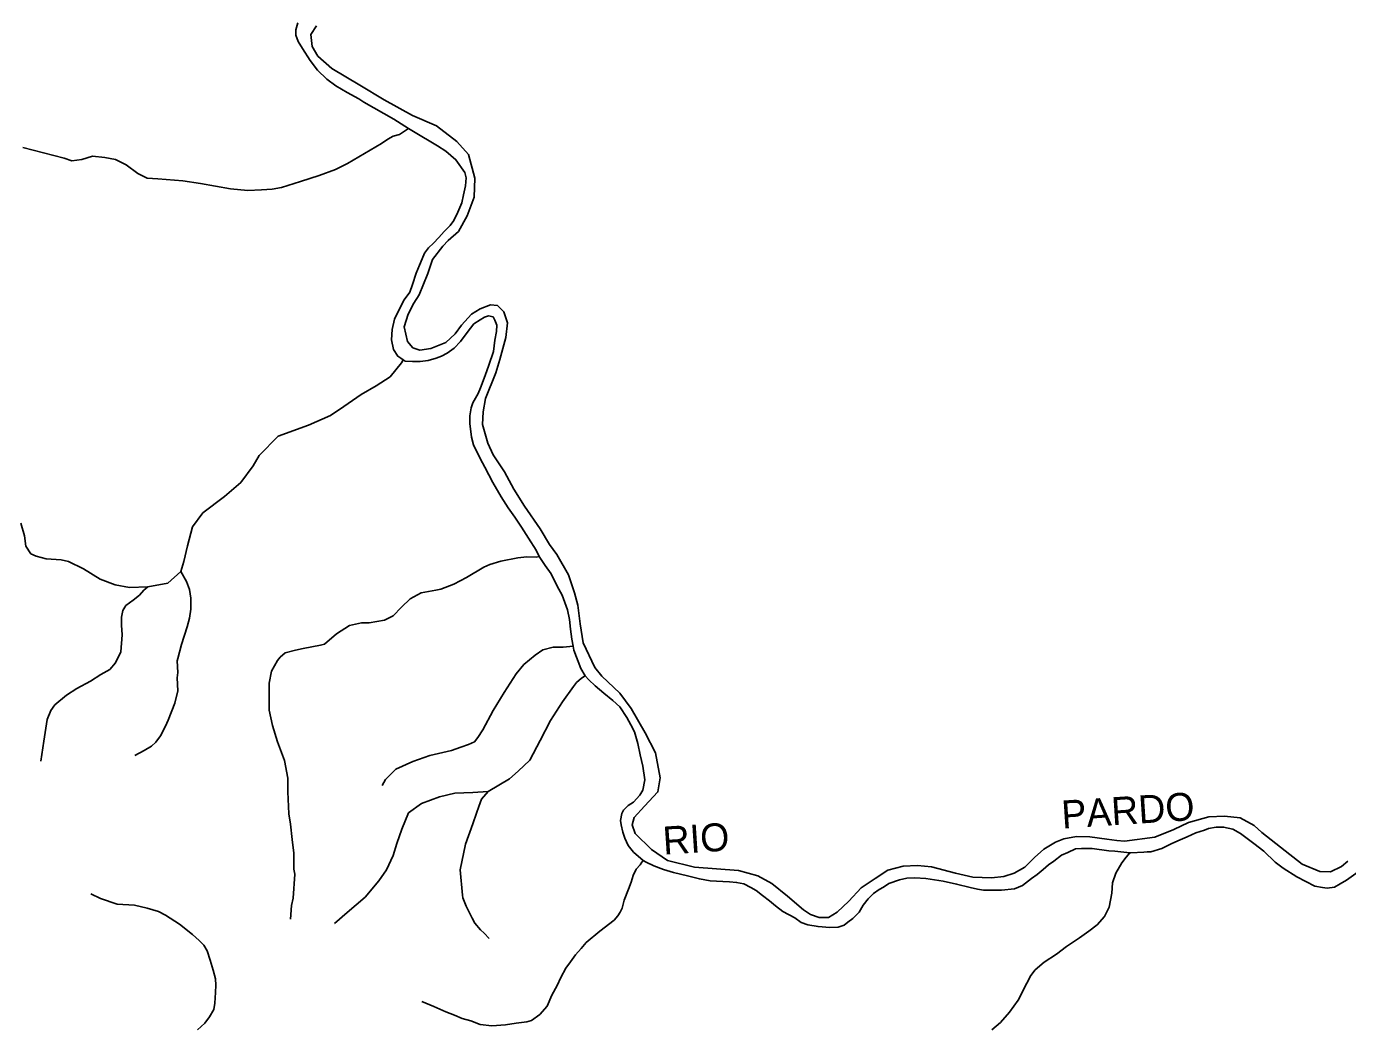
# Model space of a CAD drawing. Extents: x 436.3 to 500.4, y 8231 to 8286.4.
# Drawn here: x 483.31 to 492.75, y 8265.76 to 8272.92 of the extents above; entities that cross this region are included whole.
import ezdxf
from ezdxf.enums import TextEntityAlignment as Align

# ---------------------------------------------------------------- set-up
doc = ezdxf.new("R2010")
doc.units = 0
doc.header["$LTSCALE"] = 0.08
doc.linetypes.add('LONG_DASHED', pattern=[7.5, 6, -1.5])
doc.layers.add('2', color=7, linetype='Continuous', lineweight=25)
doc.layers.add('9', color=7, linetype='LONG_DASHED', lineweight=25)
doc.layers.add('61', color=7, linetype='Continuous')

msp = doc.modelspace()

# ---------------------------------------------------------------- linework, layer by layer
at = {"layer": '2'}
for points in [[(486.0404, 8272.1863), (485.9354, 8272.2526), (485.7207, 8272.3743), (485.6844, 8272.3972), (485.6006, 8272.443), (485.5205, 8272.4909), (485.4557, 8272.5386), (485.389, 8272.6016), (485.3376, 8272.6724), (485.2824, 8272.7584), (485.2518, 8272.8081), (485.2355, 8272.8515), (485.2337, 8272.8897), (485.2489, 8272.9413)], [(488.0829, 8266.9074), (487.8892, 8266.9559), (487.7758, 8267.0349), (487.6591, 8267.1491), (487.6361, 8267.21), (487.6514, 8267.2634), (487.7252, 8267.3446), (487.82, 8267.4463), (487.8366, 8267.5464), (487.8031, 8267.7243), (487.7304, 8267.8688), (487.6299, 8268.0412), (487.5495, 8268.1507), (487.4211, 8268.2729), (487.3709, 8268.3341), (487.2871, 8268.5122), (487.2648, 8268.6458), (487.2481, 8268.7794), (487.2259, 8268.8686), (487.1813, 8268.9967), (487.0976, 8269.1415), (487.0475, 8269.2139), (486.9805, 8269.3253), (486.869, 8269.4869), (486.791, 8269.6095), (486.7241, 8269.7322), (486.6447, 8269.8538), (486.6058, 8269.9375), (486.5669, 8270.0715), (486.5726, 8270.1608), (486.5896, 8270.2558), (486.6625, 8270.4402), (486.6905, 8270.5352), (486.7356, 8270.6917), (486.7469, 8270.7979), (486.7191, 8270.8761), (486.6745, 8270.9207), (486.6242, 8270.9263), (486.5515, 8270.8983), (486.49, 8270.8592), (486.4172, 8270.7808), (486.3724, 8270.7193), (486.3053, 8270.6578), (486.199, 8270.6129), (486.1208, 8270.6017), (486.0706, 8270.6184), (486.0315, 8270.6631), (486.0093, 8270.7693), (486.0374, 8270.8588), (486.0767, 8270.9371), (486.1159, 8270.9986), (486.1776, 8271.1496), (486.2113, 8271.2504), (486.2841, 8271.3454), (486.3232, 8271.3846), (486.3957, 8271.4502), (486.4573, 8271.5621), (486.5077, 8271.6963), (486.5135, 8271.8306), (486.4683, 8271.9989), (486.3853, 8272.0936), (486.2402, 8272.2055), (486.067, 8272.2782), (485.8659, 8272.3902), (485.6928, 8272.4965), (485.4918, 8272.6141), (485.3913, 8272.7037), (485.3522, 8272.7708), (485.3408, 8272.8566), (485.3818, 8272.9204)], [(486.4522, 8271.8331), (486.4423, 8271.8706), (486.3776, 8271.9623), (486.3071, 8272.0234), (486.2461, 8272.0616), (486.0756, 8272.1645), (486.0404, 8272.1863)], [(486.3373, 8271.4932), (486.3641, 8271.5295), (486.3928, 8271.5887), (486.4196, 8271.6536), (486.433, 8271.711), (486.4464, 8271.7759), (486.4522, 8271.8331)], [(486.0023, 8270.5329), (485.9853, 8270.5441), (485.9632, 8270.5588), (485.9328, 8270.6065), (485.9176, 8270.6771), (485.9235, 8270.7496), (485.9389, 8270.8241), (485.9733, 8270.8928), (486.0078, 8270.9616), (486.0501, 8271.0163), (486.0692, 8271.0718), (486.0941, 8271.1519), (486.1171, 8271.2092), (486.1362, 8271.2551), (486.1534, 8271.2951), (486.1822, 8271.3333), (486.2185, 8271.3658), (486.2552, 8271.4073), (486.2934, 8271.4493), (486.3373, 8271.4932)], [(486.9715, 8269.1282), (486.9505, 8269.1742), (486.8969, 8269.2591), (486.8455, 8269.3371), (486.7998, 8269.4094), (486.7522, 8269.4759), (486.7008, 8269.554), (486.6418, 8269.6568), (486.5845, 8269.7665), (486.5502, 8269.8274), (486.5046, 8269.9265), (486.4894, 8269.9817), (486.4763, 8270.077), (486.4783, 8270.1323), (486.486, 8270.1895), (486.4994, 8270.2257), (486.5379, 8270.2918), (486.5532, 8270.3338), (486.5878, 8270.4215), (486.6126, 8270.496), (486.6453, 8270.5932), (486.6568, 8270.6734), (486.6683, 8270.7344), (486.6703, 8270.7801), (486.6571, 8270.8165), (486.6438, 8270.8393), (486.6113, 8270.8469), (486.5828, 8270.8374), (486.5512, 8270.8189), (486.5053, 8270.7901), (486.4594, 8270.7272), (486.4097, 8270.6642), (486.3658, 8270.6164), (486.3161, 8270.5801), (486.2742, 8270.5591), (486.236, 8270.5438), (486.1787, 8270.5285), (486.1234, 8270.5208), (486.0681, 8270.5208), (486.0147, 8270.5246), (486.0023, 8270.5329)], [(487.2149, 8268.4865), (487.2058, 8268.5365), (487.1965, 8268.6081), (487.1889, 8268.6785), (487.1751, 8268.7465), (487.137, 8268.8511), (487.1009, 8268.9156), (487.059, 8269.0031), (487.0149, 8269.0647), (486.9715, 8269.1282)], [(487.3004, 8268.2765), (487.2708, 8268.327), (487.2207, 8268.4583), (487.2149, 8268.4865)], [(487.6072, 8267.0631), (487.5842, 8267.1163), (487.5709, 8267.158), (487.5575, 8267.211), (487.5537, 8267.2415), (487.5631, 8267.2908), (487.5745, 8267.3155), (487.6091, 8267.3491), (487.6454, 8267.372), (487.6911, 8267.4232), (487.7139, 8267.4593), (487.7271, 8267.5315), (487.7137, 8267.6301), (487.6947, 8267.7118), (487.6774, 8267.7915), (487.6523, 8267.8742), (487.6275, 8267.9254), (487.599, 8267.9766), (487.5494, 8268.0545), (487.4998, 8268.0981), (487.435, 8268.1511), (487.3717, 8268.2036), (487.3279, 8268.2468), (487.3004, 8268.2765)], [(492.7476, 8266.9504), (492.7029, 8266.9136), (492.6248, 8266.8747), (492.5468, 8266.8781), (492.421, 8266.931), (492.2676, 8267.0505), (492.1337, 8267.1562), (492.0778, 8267.2062), (491.9774, 8267.2619), (491.8658, 8267.2731), (491.7544, 8267.2675), (491.6095, 8267.2286), (491.5038, 8267.1786), (491.3702, 8267.123), (491.1529, 8267.0953), (491.0988, 8267.0984), (491.0264, 8267.1096), (490.9039, 8267.1263), (490.8092, 8267.1264), (490.7201, 8267.1097), (490.6589, 8267.0875), (490.5754, 8267.0375), (490.5087, 8266.9763), (490.4419, 8266.9096), (490.364, 8266.8651), (490.2916, 8266.8429), (490.2026, 8266.8319), (490.0688, 8266.8375), (489.9464, 8266.8653), (489.7736, 8266.9098), (489.6733, 8266.9209), (489.573, 8266.9153), (489.4617, 8266.8876), (489.3726, 8266.8264), (489.2724, 8266.7598), (489.1834, 8266.6653), (489.1, 8266.5874), (489.0387, 8266.5485), (488.9718, 8266.5485), (488.9105, 8266.5707), (488.8603, 8266.604)], [(492.8209, 8266.8747), (492.739, 8266.8158), (492.6934, 8266.7892), (492.6534, 8266.7665), (492.6001, 8266.7589), (492.5677, 8266.7627), (492.5115, 8266.7731), (492.3839, 8266.8396), (492.2867, 8266.9003), (492.2276, 8266.944), (492.1475, 8267.0219), (492.077, 8267.0769), (491.9818, 8267.1491), (491.9253, 8267.1792), (491.8605, 8267.1944), (491.8073, 8267.1944), (491.7521, 8267.1849), (491.7236, 8267.1735), (491.6628, 8267.1546), (491.6001, 8267.1262), (491.5335, 8267.0957), (491.486, 8267.0749), (491.4194, 8267.0407), (491.3406, 8267.0178), (491.3141, 8267.0178), (491.2906, 8267.0166), (491.1988, 8267.0119), (491.1911, 8267.0115)], [(487.7143, 8266.9565), (487.6453, 8267.0158), (487.6072, 8267.0631)], [(491.1911, 8267.0115), (491.084, 8267.0236), (491.0403, 8267.0255), (490.9205, 8267.0426), (490.8444, 8267.0427), (490.8026, 8267.0389), (490.7475, 8267.0124), (490.7019, 8266.9934), (490.6468, 8266.9517), (490.6107, 8266.925), (490.5727, 8266.8909), (490.5291, 8266.8549), (490.4892, 8266.8265), (490.4233, 8266.7765), (490.3682, 8266.7536), (490.2731, 8266.7442), (490.2085, 8266.7442), (490.1458, 8266.7442), (490.102, 8266.7518), (490.0507, 8266.7633), (489.9537, 8266.788), (489.8567, 8266.8089), (489.7332, 8266.8279), (489.656, 8266.8331), (489.597, 8266.8293), (489.5458, 8266.8179), (489.4697, 8266.7914), (489.4317, 8266.7667), (489.3994, 8266.7477), (489.3595, 8266.7211), (489.3216, 8266.6832), (489.2874, 8266.6358), (489.2569, 8266.5864), (489.2133, 8266.5428), (489.1772, 8266.5163), (489.1506, 8266.4935), (489.1069, 8266.4803), (489.048, 8266.4765), (488.9642, 8266.484), (488.8919, 8266.4973), (488.8443, 8266.5124), (488.7986, 8266.5465), (488.7117, 8266.5912), (488.6603, 8266.633), (488.6164, 8266.669), (488.5669, 8266.705), (488.5211, 8266.7409), (488.485, 8266.7638), (488.4336, 8266.7884), (488.3821, 8266.7997), (488.3326, 8266.8035), (488.285, 8266.8053), (488.1936, 8266.8109), (488.1174, 8266.8241), (488.0323, 8266.8456), (487.9313, 8266.8701)], [(487.9313, 8266.8701), (487.8608, 8266.8909), (487.7907, 8266.9191), (487.7357, 8266.945), (487.7143, 8266.9565)], [(488.8603, 8266.604), (488.7469, 8266.7024), (488.6352, 8266.7912), (488.5348, 8266.8467), (488.3953, 8266.8855), (488.2391, 8266.8965), (488.0829, 8266.9074)]]:
    msp.add_lwpolyline(points, dxfattribs=at)
at = {"layer": '9'}
for p, q in [((486.9509, 8269.1227), (486.9715, 8269.1282)), ((487.2737, 8268.2597), (487.3004, 8268.2765))]:
    msp.add_line(p, q, dxfattribs=at)
for points in [[(486.0404, 8272.1863), (485.9756, 8272.1439), (485.9302, 8272.1311), (485.8921, 8272.1093), (485.8468, 8272.0784), (485.6037, 8271.9358), (485.5188, 8271.8932), (485.4009, 8271.8506), (485.2688, 8271.808), (485.1319, 8271.7654), (485.0659, 8271.7512), (484.9905, 8271.7465), (484.8915, 8271.7417), (484.769, 8271.7558), (484.5549, 8271.794), (484.4276, 8271.8129), (484.2485, 8271.827), (484.1731, 8271.8317), (484.1072, 8271.8647), (484.0225, 8271.9261), (483.9471, 8271.9638), (483.8718, 8271.978), (483.7823, 8271.9874), (483.7068, 8271.9637), (483.6362, 8271.9542), (483.5796, 8271.9731), (483.286, 8272.0493)], [(484.4141, 8269.021), (484.4358, 8269.0915), (484.462, 8269.2044), (484.497, 8269.3389), (484.571, 8269.4388), (484.7248, 8269.5574), (484.8422, 8269.6574), (484.9293, 8269.7748), (484.9728, 8269.8487), (485.1078, 8269.9878), (485.3251, 8270.0662), (485.4815, 8270.1358), (485.5787, 8270.1994), (485.7005, 8270.2863), (485.8091, 8270.3472), (485.9092, 8270.4125), (485.9896, 8270.5115), (486.0023, 8270.5329)], [(483.271, 8269.3672), (483.2982, 8269.2758), (483.3072, 8269.2027), (483.3436, 8269.1479), (483.3801, 8269.1296), (483.4531, 8269.1114), (483.5592, 8269.1041), (483.6112, 8269.0911), (483.7196, 8269.0391), (483.8366, 8268.9654), (483.945, 8268.9263), (484.0463, 8268.9057), (484.1775, 8268.9102)], [(485.197, 8266.5363), (485.203, 8266.6334), (485.2152, 8266.6879), (485.2272, 8266.8578), (485.2211, 8266.8941), (485.2209, 8267.0094), (485.2086, 8267.1065), (485.1962, 8267.2157), (485.1839, 8267.2884), (485.1777, 8267.4463), (485.1777, 8267.5434), (485.1532, 8267.6709), (485.1043, 8267.8044), (485.0676, 8267.9198), (485.0433, 8268.0292), (485.0433, 8268.1203), (485.0433, 8268.2237), (485.0616, 8268.309), (485.1047, 8268.3855), (485.123, 8268.4099), (485.1597, 8268.4404), (485.233, 8268.4587), (485.2879, 8268.4711), (485.4101, 8268.4956), (485.4406, 8268.5018), (485.5261, 8268.575), (485.6177, 8268.636), (485.7036, 8268.6549), (485.7585, 8268.655), (485.8684, 8268.6734), (485.9295, 8268.704), (485.9906, 8268.7649), (486.0517, 8268.826), (486.131, 8268.8687), (486.2348, 8268.8872), (486.2715, 8268.8934), (486.363, 8268.9301), (486.4546, 8268.9789), (486.5767, 8269.0522), (486.6195, 8269.0706), (486.6988, 8269.095), (486.8208, 8269.1195), (486.8841, 8269.1261), (486.9509, 8269.1227)], [(484.0863, 8267.7067), (484.1518, 8267.7415), (484.2042, 8267.772), (484.2347, 8267.8024), (484.2696, 8267.846), (484.3046, 8267.9156), (484.322, 8267.9591), (484.3702, 8268.081), (484.3924, 8268.1693), (484.3881, 8268.2607), (484.3925, 8268.2999), (484.3882, 8268.3827), (484.3926, 8268.4001), (484.419, 8268.4995), (484.4584, 8268.6259), (484.476, 8268.687), (484.4849, 8268.7524), (484.485, 8268.8308), (484.4763, 8268.8919), (484.4546, 8268.9485), (484.4141, 8269.021)], [(484.1775, 8268.9102), (484.3209, 8268.9381), (484.4141, 8269.021)], [(483.4139, 8267.6657), (483.4352, 8267.8076), (483.4494, 8267.9019), (483.4581, 8267.9628), (483.4844, 8268.0281), (483.5149, 8268.0671), (483.5978, 8268.1368), (483.6719, 8268.1846), (483.7679, 8268.2369), (483.8421, 8268.2848), (483.9076, 8268.3196), (483.9469, 8268.3676), (483.9862, 8268.4459), (483.9951, 8268.568), (483.9909, 8268.6377), (483.991, 8268.6943), (483.9998, 8268.7423), (484.0217, 8268.7772), (484.0741, 8268.8165), (484.1177, 8268.8514), (484.1483, 8268.8863), (484.1775, 8268.9102)], [(485.8511, 8267.4922), (485.8754, 8267.5347), (485.9487, 8267.6078), (486.0708, 8267.6627), (486.1929, 8267.7055), (486.3454, 8267.7423), (486.4126, 8267.7667), (486.4675, 8267.7851), (486.5102, 8267.8033), (486.5346, 8267.8338), (486.5712, 8267.8886), (486.6444, 8268.0284), (486.7237, 8268.1563), (486.8092, 8268.2902), (486.8641, 8268.3571), (486.9435, 8268.4242), (486.9984, 8268.4608), (487.0715, 8268.4791), (487.1447, 8268.4792), (487.2149, 8268.4865)], [(486.6081, 8267.4487), (486.7606, 8267.54), (486.8216, 8267.5948), (486.9069, 8267.6739), (486.9801, 8267.8138), (487.0539, 8267.9563), (487.1392, 8268.0902), (487.2185, 8268.1997), (487.2385, 8268.227), (487.2737, 8268.2597)], [(485.5101, 8266.5059), (485.6016, 8266.5849), (485.7297, 8266.6944), (485.8272, 8266.8097), (485.8821, 8266.8888), (485.9308, 8266.992), (485.9552, 8267.0769), (485.9917, 8267.1802), (486.0405, 8267.2956), (486.132, 8267.3626), (486.2602, 8267.4115), (486.3701, 8267.436), (486.4983, 8267.4424), (486.6081, 8267.4487)], [(486.6159, 8266.3995), (486.5793, 8266.4358), (486.5548, 8266.46), (486.512, 8266.5085), (486.4936, 8266.5448), (486.4508, 8266.6296), (486.4263, 8266.6903), (486.4262, 8266.7084), (486.4078, 8266.8904), (486.446, 8267.0728), (486.4985, 8267.2186), (486.5249, 8267.2944), (486.5424, 8267.341), (486.5599, 8267.3936), (486.6081, 8267.4487)], [(486.1354, 8265.9482), (486.221, 8265.912), (486.3065, 8265.8758), (486.3676, 8265.8517), (486.4226, 8265.8275), (486.4837, 8265.8095), (486.5509, 8265.7854), (486.6344, 8265.7753), (486.7328, 8265.783), (486.8086, 8265.7932), (486.8844, 8265.8034), (486.9172, 8265.8134), (486.9777, 8265.8562), (487.0307, 8265.9165), (487.0633, 8265.9943), (487.1011, 8266.0621), (487.1263, 8266.1198), (487.164, 8266.1876), (487.1968, 8266.2328), (487.232, 8266.2831), (487.2724, 8266.3283), (487.3076, 8266.371), (487.4067, 8266.4504), (487.5074, 8266.5308), (487.5352, 8266.5609), (487.5503, 8266.5861), (487.5654, 8266.6162), (487.5804, 8266.6715), (487.6106, 8266.7518), (487.6307, 8266.802), (487.6433, 8266.8498), (487.6659, 8266.895), (487.6936, 8266.9252), (487.7061, 8266.9449), (487.7143, 8266.9565)], [(490.2045, 8265.7467), (490.2674, 8265.7982), (490.3317, 8265.872), (490.3927, 8265.9587), (490.4547, 8266.0792), (490.4837, 8266.1337), (490.515, 8266.1744), (490.58, 8266.2301), (490.6669, 8266.2879), (490.7377, 8266.3425), (490.8309, 8266.4035), (490.8984, 8266.4516), (490.9567, 8266.4975), (491.0106, 8266.5552), (491.0435, 8266.6224), (491.0626, 8266.722), (491.0657, 8266.796), (491.0914, 8266.8666), (491.1332, 8266.9405), (491.1654, 8266.9791), (491.1911, 8267.0115)], [(483.7716, 8266.7169), (483.8405, 8266.6848), (483.9578, 8266.6446), (484.0832, 8266.6367), (484.1722, 8266.6166), (484.2532, 8266.5926), (484.3037, 8266.5645), (484.405, 8266.5002), (484.4961, 8266.4281), (484.5448, 8266.3839), (484.5772, 8266.3518), (484.6015, 8266.3116), (484.6239, 8266.2433), (484.6444, 8266.172), (484.6608, 8266.1117), (484.6628, 8266.0655), (484.6609, 8266.0133), (484.6569, 8265.9368), (484.6489, 8265.8927), (484.6186, 8265.8403), (484.5843, 8265.7942), (484.5337, 8265.7459)]]:
    msp.add_lwpolyline(points, dxfattribs=at)

# ---------------------------------------------------------------- texts
at = {"layer": '61'}
msp.add_text('RIO                                PARDO', height=0.2, rotation=3.747, dxfattribs=at).set_placement((489.7598, 8267.1216), align=Align.CENTER)

doc.saveas('drawing.dxf')
